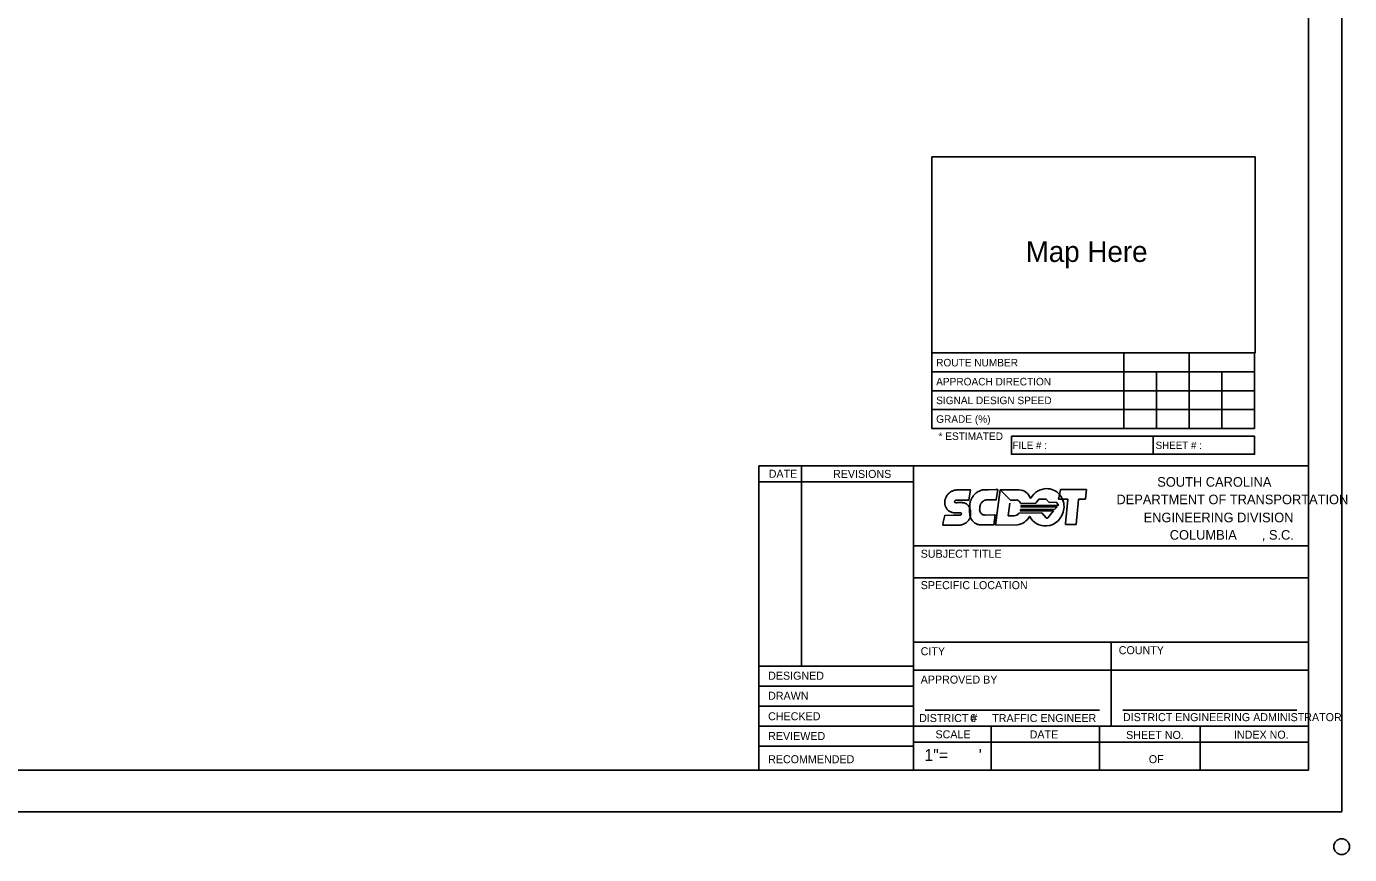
# Model space of a CAD drawing. Extents: x 0 to 3.01, y -0.05 to 1.83.
# Drawn here: x 1.504 to 3.009, y -0.048 to 0.892 of the extents above; entities that cross this region are included whole.
import ezdxf

# ---------------------------------------------------------------- set-up
doc = ezdxf.new("R2010")
doc.units = 0
doc.layers.add('RD_SHT_IplotShp', color=7, linetype='Continuous')
doc.layers.add('TR_TS_Border', color=7, linetype='Continuous')

msp = doc.modelspace()

# ---------------------------------------------------------------- linework, layer by layer
at = {"layer": 'RD_SHT_IplotShp'}
msp.add_lwpolyline([(0, 0), (3, 0), (3, 1.8333), (0, 1.8333)], close=True, dxfattribs=at)
at = {"layer": 'TR_TS_Border'}
for p, q in [((3, 0), (3, 1.8333)), ((2.9623, 0.0475), (2.9623, 1.7754)), ((2.5341, 0.5215), (2.9009, 0.5215)), ((2.5341, 0.4357), (2.5341, 0.5215)), ((2.7521, 0.4357), (2.7521, 0.5215)), ((2.8265, 0.4357), (2.8265, 0.5215)), ((2.9009, 0.4357), (2.9009, 0.5215)), ((2.5341, 0.5), (2.9009, 0.5)), ((2.7893, 0.4357), (2.7893, 0.5)), ((2.8637, 0.4357), (2.8637, 0.5)), ((2.5341, 0.4786), (2.9009, 0.4786)), ((2.5341, 0.4571), (2.9009, 0.4571)), ((2.5341, 0.4357), (2.9009, 0.4357)), ((2.7857, 0.4268), (2.7857, 0.4064)), ((2.3372, 0.3932), (2.9623, 0.3932)), ((2.3372, 0.0475), (2.3372, 0.3932)), ((2.3856, 0.3932), (2.3856, 0.1657)), ((2.5133, 0.0475), (2.5133, 0.3932)), ((2.3372, 0.375), (2.5133, 0.375)), ((2.6065, 0.3259), (2.6116, 0.3661)), ((2.6233, 0.3544), (2.6116, 0.3661)), ((2.6116, 0.3661), (2.6334, 0.366)), ((2.6116, 0.3661), (2.6233, 0.3544)), ((2.6802, 0.3659), (2.678, 0.3555)), ((2.6803, 0.3663), (2.6802, 0.3659)), ((2.6809, 0.3664), (2.6804, 0.3664)), ((2.7089, 0.3665), (2.6809, 0.3664)), ((2.7086, 0.3556), (2.7099, 0.3665)), ((2.7096, 0.3665), (2.7089, 0.3665)), ((2.7099, 0.3665), (2.7096, 0.3665)), ((2.6227, 0.3509), (2.6206, 0.3364)), ((2.6298, 0.3544), (2.6233, 0.3544)), ((2.6522, 0.3507), (2.6349, 0.3506)), ((2.6353, 0.348), (2.677, 0.3483)), ((2.6758, 0.3466), (2.6353, 0.3464)), ((2.6557, 0.3554), (2.6522, 0.3507)), ((2.6638, 0.3554), (2.6557, 0.3554)), ((2.6674, 0.3517), (2.6638, 0.3554)), ((2.6753, 0.3518), (2.6674, 0.3517)), ((2.6739, 0.3439), (2.676, 0.3463)), ((2.6757, 0.3517), (2.6777, 0.3493)), ((2.6757, 0.3517), (2.6777, 0.3493)), ((2.6777, 0.3493), (2.6757, 0.3517)), ((2.677, 0.3483), (2.6771, 0.3478)), ((2.6771, 0.3478), (2.6772, 0.3477)), ((2.6772, 0.3477), (2.6777, 0.3487)), ((2.678, 0.3555), (2.6882, 0.3554)), ((2.6886, 0.3549), (2.686, 0.3278)), ((2.6982, 0.3265), (2.7008, 0.3549)), ((2.7012, 0.3554), (2.7083, 0.3554)), ((2.6206, 0.3364), (2.6274, 0.3366)), ((2.633, 0.3395), (2.659, 0.3397)), ((2.672, 0.3422), (2.6345, 0.342)), ((2.6349, 0.3437), (2.6739, 0.3439)), ((2.659, 0.3397), (2.6641, 0.3342)), ((2.6659, 0.3342), (2.6721, 0.3418)), ((2.6313, 0.3261), (2.6065, 0.3259)), ((2.686, 0.3278), (2.686, 0.327)), ((2.6863, 0.3265), (2.6982, 0.3265)), ((2.9623, 0.3022), (2.5133, 0.3022)), ((2.9623, 0.2658), (2.5133, 0.2658)), ((2.9623, 0.193), (2.5133, 0.193)), ((2.7378, 0.193), (2.7378, 0.0975)), ((2.3372, 0.1657), (2.5133, 0.1657)), ((2.9623, 0.1612), (2.5133, 0.1612)), ((2.3372, 0.143), (2.5133, 0.143)), ((2.3372, 0.1203), (2.5133, 0.1203)), ((2.5265, 0.1157), (2.7246, 0.1157)), ((2.9491, 0.1157), (2.751, 0.1157)), ((2.9623, 0.0975), (2.3372, 0.0975)), ((2.6013, 0.0475), (2.6013, 0.0975)), ((2.7246, 0.0475), (2.7246, 0.0975)), ((2.8391, 0.0475), (2.8391, 0.0975)), ((2.9623, 0.0793), (2.5133, 0.0793)), ((2.3372, 0.0748), (2.5133, 0.0748)), ((0.1686, 0.0475), (2.9623, 0.0475)), ((0.0238, 0), (3, 0))]:
    msp.add_line(p, q, dxfattribs=at)
for points in [[(2.5341, 0.5215), (2.9015, 0.5215), (2.9015, 0.7443), (2.5341, 0.7443)], [(2.6244, 0.4268), (2.9009, 0.4268), (2.9009, 0.4064), (2.6244, 0.4064)]]:
    msp.add_lwpolyline(points, close=True, dxfattribs=at)
for points in [[(2.5561, 0.3406), (2.5554, 0.341), (2.5545, 0.3413), (2.5537, 0.3417), (2.553, 0.3422), (2.5523, 0.3428), (2.5517, 0.3434), (2.5513, 0.3438), (2.5507, 0.3445), (2.5505, 0.3452), (2.5501, 0.3459), (2.5496, 0.3466), (2.5494, 0.3473), (2.5491, 0.3479), (2.549, 0.3485), (2.5489, 0.3491), (2.5488, 0.3495), (2.5488, 0.3502), (2.5488, 0.3515), (2.5488, 0.3522), (2.5488, 0.3533), (2.5489, 0.3542), (2.549, 0.3549), (2.5493, 0.3558), (2.5497, 0.3566), (2.55, 0.3574), (2.5505, 0.3583), (2.5507, 0.3589), (2.5513, 0.3599), (2.552, 0.3606), (2.5527, 0.3615), (2.5535, 0.3623), (2.5542, 0.3627), (2.555, 0.3634), (2.5561, 0.364), (2.5566, 0.3643), (2.5575, 0.3646), (2.5581, 0.3649), (2.5587, 0.3652), (2.5596, 0.3655), (2.5605, 0.3656), (2.5613, 0.3657), (2.5621, 0.3658), (2.5627, 0.3658), (2.5634, 0.3658), (2.5725, 0.3659), (2.5778, 0.3659)], [(2.5778, 0.3659), (2.5759, 0.3543), (2.562, 0.3543), (2.5616, 0.3542), (2.561, 0.3541), (2.5608, 0.3539), (2.5605, 0.3537), (2.5602, 0.3535), (2.5601, 0.3534), (2.5601, 0.3532), (2.56, 0.3529), (2.5599, 0.3526), (2.5599, 0.3524), (2.5599, 0.3521), (2.56, 0.3521), (2.5601, 0.3517), (2.5602, 0.3516), (2.5604, 0.3515), (2.5608, 0.3514), (2.5609, 0.3514), (2.5614, 0.3513), (2.5624, 0.3513), (2.5634, 0.3514), (2.5641, 0.3514), (2.565, 0.3515), (2.5676, 0.3515)], [(2.5774, 0.3517), (2.5773, 0.3509), (2.5771, 0.35), (2.577, 0.3488), (2.577, 0.348), (2.577, 0.3471), (2.577, 0.3468), (2.5769, 0.3464), (2.5769, 0.3462), (2.5768, 0.3458), (2.5768, 0.3453), (2.5768, 0.345), (2.5767, 0.3446), (2.5767, 0.344), (2.5767, 0.3435), (2.5767, 0.3431), (2.5767, 0.3426), (2.5767, 0.3423), (2.5767, 0.3419), (2.5767, 0.3413), (2.5768, 0.3405), (2.5769, 0.3397), (2.577, 0.339), (2.577, 0.3383), (2.5771, 0.3375), (2.5773, 0.337), (2.5773, 0.3364), (2.5774, 0.3359), (2.5777, 0.3352), (2.5778, 0.3345), (2.5779, 0.3341), (2.5785, 0.3332), (2.579, 0.3324), (2.5793, 0.3318), (2.5798, 0.3312), (2.5803, 0.3306), (2.581, 0.3299), (2.5816, 0.3293), (2.5822, 0.3288), (2.5829, 0.3282), (2.5839, 0.3278), (2.5847, 0.3272), (2.5853, 0.327), (2.586, 0.3267), (2.5866, 0.3266), (2.5871, 0.3264), (2.588, 0.3262), (2.5884, 0.3262), (2.5891, 0.3261), (2.5896, 0.3261), (2.6042, 0.3261), (2.6043, 0.3262), (2.6043, 0.3262), (2.6058, 0.3374), (2.6053, 0.3374), (2.5945, 0.3373), (2.5935, 0.3374), (2.5927, 0.3375), (2.592, 0.3377), (2.5913, 0.3381), (2.5907, 0.3385), (2.59, 0.3392), (2.5895, 0.3398), (2.5891, 0.3403), (2.5888, 0.341), (2.5886, 0.3416), (2.5884, 0.3422), (2.5883, 0.3431), (2.5884, 0.3442), (2.5885, 0.3452), (2.5886, 0.3464), (2.5887, 0.3472), (2.5888, 0.3483), (2.5891, 0.349), (2.5895, 0.3497), (2.5898, 0.3505), (2.5903, 0.3513), (2.591, 0.3518), (2.5916, 0.3525), (2.5922, 0.3531), (2.5932, 0.3536), (2.594, 0.3541), (2.5947, 0.3543), (2.5951, 0.3544), (2.5959, 0.3545), (2.5968, 0.3545), (2.6072, 0.3545), (2.6073, 0.3546), (2.6089, 0.3665)], [(2.6089, 0.3665), (2.6067, 0.3665), (2.5985, 0.3661), (2.5958, 0.3661), (2.5941, 0.3661), (2.593, 0.366), (2.5916, 0.3658), (2.5907, 0.3656), (2.5899, 0.3654), (2.5889, 0.3649), (2.588, 0.3645), (2.5868, 0.364), (2.5857, 0.3633), (2.5845, 0.3624), (2.5841, 0.3621), (2.5834, 0.3615), (2.5825, 0.3608), (2.5818, 0.36), (2.581, 0.359), (2.5805, 0.3581), (2.5799, 0.3573), (2.5795, 0.3566), (2.5791, 0.3558), (2.5787, 0.355), (2.5782, 0.3541), (2.5779, 0.3533), (2.5777, 0.3524), (2.5774, 0.3517)], [(2.5767, 0.3466), (2.5769, 0.3462), (2.577, 0.3458), (2.5771, 0.3454), (2.5771, 0.3452), (2.5773, 0.3448), (2.5774, 0.3443), (2.5775, 0.344), (2.5775, 0.3438), (2.5776, 0.3435), (2.5777, 0.3433), (2.5777, 0.3431), (2.5777, 0.3429), (2.5778, 0.3427), (2.5778, 0.3423), (2.5778, 0.342), (2.5778, 0.3417), (2.5779, 0.3415), (2.5779, 0.3412), (2.5779, 0.341), (2.578, 0.3406), (2.578, 0.3403), (2.578, 0.3399), (2.578, 0.3396), (2.578, 0.3396), (2.578, 0.3392), (2.578, 0.3389), (2.578, 0.3385), (2.578, 0.3383), (2.578, 0.3382), (2.578, 0.338), (2.578, 0.3376), (2.578, 0.3373), (2.5779, 0.3371), (2.5779, 0.3367), (2.5779, 0.3364), (2.5778, 0.3362), (2.5778, 0.3359), (2.5778, 0.3357), (2.5777, 0.3354), (2.5776, 0.3352), (2.5776, 0.3349), (2.5775, 0.3347), (2.5774, 0.3344), (2.5773, 0.334), (2.5771, 0.3336), (2.5769, 0.3329), (2.5766, 0.3325), (2.5762, 0.3321), (2.576, 0.3318), (2.5756, 0.3313), (2.5752, 0.3307), (2.5746, 0.3301), (2.5738, 0.3292), (2.573, 0.3286), (2.5719, 0.328), (2.5708, 0.3272), (2.5699, 0.3269), (2.569, 0.3265), (2.5682, 0.3262), (2.5673, 0.3261), (2.5663, 0.3259), (2.5657, 0.3259), (2.557, 0.3257), (2.5466, 0.3257), (2.5464, 0.3259), (2.5464, 0.3259), (2.5464, 0.3261), (2.5464, 0.3262), (2.547, 0.3291), (2.5486, 0.3367), (2.5486, 0.3368), (2.5488, 0.337), (2.5488, 0.337), (2.5492, 0.3368), (2.5588, 0.337), (2.5654, 0.337), (2.5659, 0.3371), (2.5662, 0.3371), (2.5666, 0.3372), (2.567, 0.3374), (2.5672, 0.3377), (2.5674, 0.3379), (2.5675, 0.3383), (2.5676, 0.3386), (2.5676, 0.339), (2.5676, 0.3392), (2.5675, 0.3392), (2.5675, 0.3394), (2.5674, 0.3396), (2.5672, 0.3398), (2.5669, 0.3399), (2.5667, 0.34), (2.5666, 0.34), (2.5594, 0.3399), (2.559, 0.3399), (2.5587, 0.34), (2.5582, 0.34), (2.5578, 0.3402), (2.5568, 0.3403), (2.5561, 0.3406)], [(2.5676, 0.3515), (2.5684, 0.3514), (2.5692, 0.3513), (2.5699, 0.3512), (2.5708, 0.351), (2.5714, 0.3508), (2.572, 0.3505), (2.5725, 0.3503), (2.5732, 0.3499), (2.574, 0.3494), (2.5745, 0.349), (2.575, 0.3487), (2.5754, 0.3483), (2.5759, 0.3476), (2.5762, 0.3473), (2.5766, 0.3468), (2.5767, 0.3466)]]:
    msp.add_lwpolyline(points, dxfattribs=at)
msp.add_circle((3, -0.0395), 0.00894, dxfattribs=at)
for centre, major_axis, start_param, end_param in [((2.6326, 0.3507), (0, 0.0153), 5.101309, 6.228759), ((2.6647, 0.3449), (0, 0.0224), 0.022191, 1.026566), ((2.6648, 0.3468), (0, 0.0205), 4.590524, 6.310821), ((2.6804, 0.3662), (0, 0.000124), 0, 1.322539), ((2.6301, 0.3493), (0, 0.0052), 4.972804, 6.356492), ((2.6232, 0.3471), (0, 0.0128), 4.666228, 4.78426), ((2.6463, 0.3566), (0, 0.000247), 1.959716, 4.168159), ((2.6753, 0.3513), (0, 0.000494), 5.415198, 6.296193), ((2.6759, 0.3465), (0, 0.000185), 3.986308, 6.285649), ((2.6773, 0.3489), (0, -0.000494), 1.075193, 2.27985), ((2.6882, 0.3549), (0, -0.000494), 1.467405, 3.132152), ((2.7012, 0.3548), (0, 0.000494), 0, 1.477178), ((2.7083, 0.3557), (0, -0.000371), 0, 1.445107), ((2.6275, 0.3439), (0, -0.00733), 6.271457, 7.213216), ((2.6283, 0.347), (0, -0.0211), 0.151273, 0.993651), ((2.6231, 0.3471), (0, -0.0129), 1.163643, 1.303168), ((2.6453, 0.3353), (0, -0.000247), 2.058368, 4.135244), ((2.6622, 0.3448), (0, -0.0199), 5.19996, 6.392752), ((2.665, 0.335), (0, -0.00124), 5.487728, 7.137097), ((2.6633, 0.347), (0, -0.022), 0.045208, 1.450715), ((2.672, 0.342), (0, 0.000247), 3.995698, 6.287734), ((2.6863, 0.3269), (0, -0.000371), 4.712389, 6.283185)]:
    msp.add_ellipse(centre, major_axis=major_axis, ratio=0.950042, start_param=start_param, end_param=end_param, dxfattribs=at)

# ---------------------------------------------------------------- texts
for s, height, p in [('Map Here', 0.02359, (2.6407, 0.6249)), ('ROUTE NUMBER', 0.008578, (2.5389, 0.5062)), ('APPROACH DIRECTION', 0.008578, (2.5389, 0.4846)), ('SIGNAL DESIGN SPEED', 0.008578, (2.5389, 0.4633)), ('GRADE (%)', 0.00858, (2.5389, 0.4421)), ('* ESTIMATED', 0.008578, (2.5416, 0.4226)), ('FILE # :', 0.00833, (2.6258, 0.4124)), ('SHEET # :', 0.00833, (2.7884, 0.4124)), ('DATE', 0.0091, (2.3485, 0.3797)), ('REVISIONS', 0.0091, (2.4216, 0.3795)), ('SOUTH CAROLINA', 0.010918, (2.7903, 0.3695)), ('DEPARTMENT OF TRANSPORTATION', 0.010918, (2.7439, 0.3496)), ('ENGINEERING DIVISION', 0.010918, (2.7748, 0.3291)), ('       COLUMBIA       , S.C.', 0.010918, (2.7761, 0.3093)), ('SUBJECT TITLE', 0.009098, (2.5213, 0.2888)), ('SPECIFIC LOCATION', 0.009098, (2.5213, 0.2531)), ('CITY', 0.0091, (2.5213, 0.178)), ('COUNTY', 0.0091, (2.7465, 0.1792)), ('DESIGNED', 0.0091, (2.3478, 0.1502)), ('APPROVED BY', 0.009098, (2.5213, 0.1458)), ('APPROVED BY', 0.009098, (2.5213, 0.1458)), ('DRAWN', 0.0091, (2.3478, 0.1274)), ('CHECKED', 0.0091, (2.3478, 0.1041)), ('DISTRICT #     TRAFFIC ENGINEER', 0.009098, (2.5195, 0.1021)), ('6', 0.0091, (2.5775, 0.1021)), ('DISTRICT ENGINEERING ADMINISTRATOR', 0.009098, (2.7513, 0.1031)), ('REVIEWED', 0.0091, (2.3478, 0.0817)), ('SCALE', 0.0091, (2.5381, 0.0836)), ('DATE', 0.0091, (2.6452, 0.0835)), ('SHEET NO.', 0.0091, (2.7549, 0.0829)), ('INDEX NO.', 0.0091, (2.8775, 0.0832)), ('RECOMMENDED', 0.009098, (2.3478, 0.0553)), ('1"=       \'', 0.013434, (2.5255, 0.0579)), ('OF', 0.0091, (2.7807, 0.0554))]:
    msp.add_text(s, height=height, dxfattribs=at).set_placement(p)

doc.saveas('drawing.dxf')
